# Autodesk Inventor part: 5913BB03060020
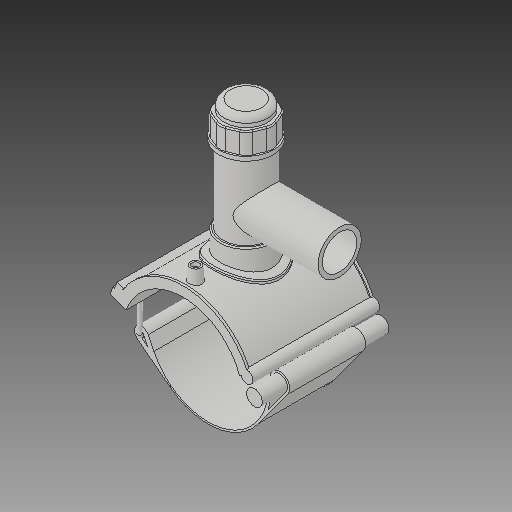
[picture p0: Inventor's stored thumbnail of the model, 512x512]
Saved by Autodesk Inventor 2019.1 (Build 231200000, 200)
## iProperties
Created: 2017-07
Part Number: 5913BB03060020
Material: Generic
Description: PLASSON HIGH VOLUME TAPPING TEE 6''IPSx 2''IPS
Document SubType Name: Modeling
Designer: KIM
Mass: 1712.7 g
Surface Area: 2671.49 cm^2
Volume: 1712.7 cm^3
Density: 1 g/cm^3
Appearance: Default
Author: KIM
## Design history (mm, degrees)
derived "5913B.ipt"
feature "Solid1::5913B.ipt"
feature "Solid2::5913B.ipt"
feature "Solid4::5913B.ipt"
feature "Solid5::5913B.ipt"
tag "TaggingFeature1"
body "Solid1"
body "Solid2"
other parameters: "d0" = 168, "d2" = 432.435, "d3" = 42, "d4" = 176.022, "d5" = 0, "d6" = 0.1, "d8" = 0, "d40" = 99.5904, "d41" = 92.4, "d43" = 0, "d45" = 0, "d47" = 201.3732, "d78" = 114, "d79" = 15, "d80" = 70.4088, "d82" = 5 deg, "d84" = 4, "d85" = 14, "d86" = 0, "d87" = 3, "d88" = 0, "d96" = 195.3504, "d97" = 3.52044, "d98" = 0, "d102" = 1.68, "d120" = 140 deg, "d121" = 24.228, "d122" = 20 deg, "d123" = 478.8, "d124" = 114.912, "d126" = 0, "d153" = 176.022, "d154" = 0, "d159" = 4.704, "d162" = 105.6132, "d163" = 0, "d164" = 84, "d169" = 4.0905, "d170" = 7.056, "d172" = 0, "d173" = 1, "d175" = 84, "d176" = 20 deg, "d177" = 11.76, "d178" = 23.52, "d180" = 0, "d183" = 9.408, "d184" = 9.408, "d187" = 95.76, "d188" = 7.056, "d189" = 11.76, "d190" = 0, "d191" = 143.64, "d193" = 6.048, "d194" = 3.024, "d195" = 90 deg, "d197" = 0, "d199" = 0, "d200" = 11.76, "d202" = 0, "d203" = 194.818, "d204" = 71.9796, "d205" = 53.0376, "d206" = 64.4028, "d207" = 146.1135, "d208" = 151.95804, "d209" = 181.18074, "d210" = 65.16048, "d211" = 75.768, "d212" = 60.6144, "d213" = 40.392, "d216" = 0, "d217" = 16.8, "d218" = 8.4, "d219" = 1.68, "d222" = 168, "d224" = 0, "d230" = 1.68, "d257" = 158.93, "d258" = 129.794, "d259" = 48.08, "d260" = 60.1, "d263" = 172.974, "d265" = 0, "d267" = 13.00006, "d268" = 2.60001, "d269" = 2.60001, "d271" = 2.60001, "d273" = 0, "d274" = 23.56194, "d275" = 134.4, "d277" = 67.2, "d278" = 268.8, "d280" = 0, "d281" = 168, "d283" = 0, "d285" = 0, "d290" = 16.8, "d291" = 21.84, "d293" = 92.4, "d294" = 86.52, "d296" = 25.2, "d297" = 20.16, "d_" = 168, "B_" = 172.974, "L_" = 176.022, "d_t" = 6, "H_2" = 194.818, "H_1" = 74.93, "d_1" = 60.1, "H_" = 129.794, "d1" = 191.52, "d192" = 6.048
